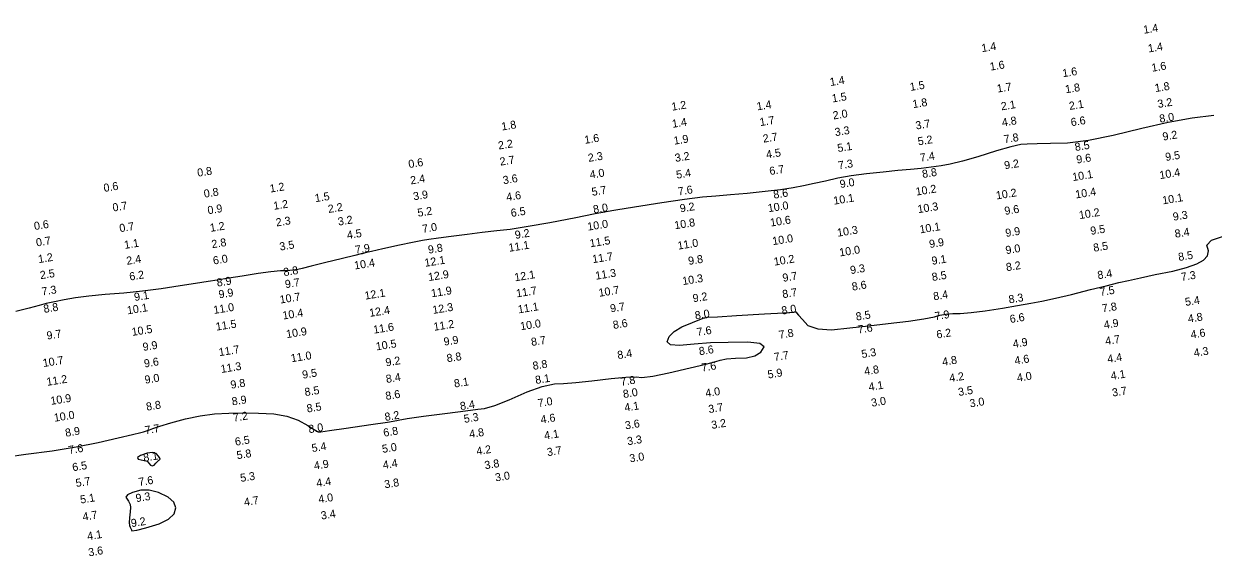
# Model space of a CAD drawing. Extents: x 988130 to 1132882, y 654656 to 841453.
# Drawn here: x 1107874 to 1108617, y 666534 to 666867 of the extents above; entities that cross this region are included whole.
import ezdxf

# ---------------------------------------------------------------- set-up
doc = ezdxf.new("R2010")
doc.units = 0
doc.layers.add('V-TOPO-MAJR', color=7, linetype='Continuous')
doc.layers.add('V-TOPO-SOUN', color=7, linetype='Continuous')

msp = doc.modelspace()

# ---------------------------------------------------------------- linework, layer by layer
at = {"layer": 'V-TOPO-MAJR'}
for points in [[(1108617.19, 666809.85), (1108603.62, 666808.13), (1108588.62, 666805.46), (1108572.17, 666801.85), (1108554.27, 666797.3), (1108538.79, 666794.21), (1108525.72, 666792.58), (1108515.07, 666792.43), (1108506.66, 666792.23), (1108500.51, 666791.99), (1108496.61, 666791.72), (1108490.18, 666790.31), (1108481.23, 666787.75), (1108469.76, 666784.06), (1108460.17, 666781.28), (1108452.48, 666779.4), (1108446.66, 666778.42), (1108440.57, 666777.57), (1108434.18, 666776.84), (1108427.51, 666776.22), (1108419.6, 666775.45), (1108410.44, 666774.53), (1108400.04, 666773.45), (1108390.59, 666772.15), (1108382.11, 666770.64), (1108374.58, 666768.92), (1108367.44, 666767.35), (1108360.69, 666765.94), (1108354.33, 666764.69), (1108346.33, 666763.48), (1108336.7, 666762.31), (1108325.44, 666761.2), (1108315.18, 666760.24), (1108305.92, 666759.44), (1108297.67, 666758.79), (1108286.46, 666757.43), (1108272.29, 666755.35), (1108255.16, 666752.56), (1108243.55, 666750.68), (1108237.45, 666749.7), (1108236.87, 666749.62), (1108236.3, 666749.54), (1108235.74, 666749.44), (1108235.19, 666749.33), (1108229.42, 666748.2), (1108218.44, 666746.04), (1108202.24, 666742.87), (1108188.61, 666740.43), (1108177.54, 666738.73), (1108169.04, 666737.77), (1108160.05, 666736.7), (1108150.58, 666735.53), (1108140.61, 666734.26), (1108132.63, 666733.22), (1108126.64, 666732.4), (1108122.64, 666731.8), (1108116.51, 666730.62), (1108108.24, 666728.87), (1108097.84, 666726.53), (1108090.7, 666724.91), (1108086.8, 666723.99), (1108086.17, 666723.79), (1108085.56, 666723.63), (1108084.97, 666723.52), (1108084.42, 666723.45), (1108080.32, 666722.48), (1108072.67, 666720.6), (1108061.48, 666717.81), (1108053.11, 666715.73), (1108047.56, 666714.36), (1108044.85, 666713.69), (1108041.66, 666713.21), (1108038, 666712.89), (1108033.87, 666712.75), (1108027.83, 666712.15), (1108019.89, 666711.09), (1108010.05, 666709.56), (1108001.56, 666708.22), (1107994.44, 666707.08), (1107988.68, 666706.13), (1107980.92, 666704.91), (1107971.17, 666703.42), (1107959.43, 666701.66), (1107947.71, 666700.17), (1107936.01, 666698.95), (1107924.32, 666698.01), (1107914.24, 666696.99), (1107905.76, 666695.9), (1107898.87, 666694.73), (1107892.82, 666693.55), (1107887.59, 666692.36), (1107883.19, 666691.15), (1107876.86, 666689.52), (1107868.62, 666687.46)], [(1107863.46, 666596.67), (1107874.78, 666598.17), (1107891.23, 666600.35), (1107906.34, 666602.78), (1107920.1, 666605.47), (1107932.53, 666608.41), (1107941.38, 666610.52), (1107946.65, 666611.8), (1107948.34, 666612.24), (1107950.14, 666612.82), (1107952.06, 666613.52), (1107954.09, 666614.35), (1107958.51, 666615.78), (1107965.33, 666617.79), (1107974.54, 666620.4), (1107983.67, 666622.28), (1107992.73, 666623.44), (1108001.71, 666623.89), (1108010.87, 666624.04), (1108020.2, 666623.9), (1108029.71, 666623.47), (1108038, 666622.03), (1108045.07, 666619.57), (1108050.92, 666616.1), (1108054.9, 666613.74), (1108057.01, 666612.49), (1108057.26, 666612.36), (1108057.45, 666612.27), (1108057.6, 666612.21), (1108057.69, 666612.19), (1108057.82, 666612.18), (1108057.99, 666612.19), (1108058.2, 666612.22), (1108058.46, 666612.25), (1108058.79, 666612.27), (1108059.18, 666612.3), (1108064.56, 666613.04), (1108074.94, 666614.5), (1108090.31, 666616.68), (1108100.86, 666618.25), (1108106.6, 666619.21), (1108107.51, 666619.57), (1108113.1, 666620.46), (1108123.34, 666621.89), (1108138.26, 666623.84), (1108149.57, 666625.31), (1108157.29, 666626.28), (1108161.4, 666626.76), (1108167.91, 666628.73), (1108176.81, 666632.18), (1108188.1, 666637.13), (1108197.51, 666640.48), (1108205.05, 666642.26), (1108210.72, 666642.45), (1108218.52, 666643.04), (1108228.45, 666644.04), (1108240.51, 666645.44), (1108249.75, 666646.27), (1108256.18, 666646.53), (1108259.78, 666646.22), (1108266.6, 666647.05), (1108276.63, 666649.02), (1108289.89, 666652.13), (1108299.64, 666654.51), (1108305.87, 666656.16), (1108308.58, 666657.07), (1108312.68, 666657.77), (1108318.16, 666658.24), (1108325.02, 666658.5), (1108330.3, 666659.76), (1108333.99, 666662), (1108336.1, 666665.23), (1108333.42, 666667.33), (1108325.96, 666668.3), (1108313.72, 666668.13), (1108302.52, 666667.72), (1108292.37, 666667.07), (1108283.25, 666666.18), (1108277.63, 666666.66), (1108275.5, 666668.52), (1108276.86, 666671.74), (1108279.96, 666674.81), (1108284.81, 666677.73), (1108291.4, 666680.49), (1108296, 666682.37), (1108298.59, 666683.38), (1108299.18, 666683.51), (1108299.76, 666683.62), (1108300.31, 666683.71), (1108300.84, 666683.78), (1108307.04, 666684.17), (1108318.91, 666684.88), (1108336.44, 666685.91), (1108348.36, 666686.63), (1108354.68, 666687.04), (1108355.39, 666687.14), (1108355.93, 666687.1), (1108356.28, 666686.92), (1108356.45, 666686.6), (1108357.71, 666685.12), (1108360.07, 666682.47), (1108363.53, 666678.66), (1108369.6, 666676.51), (1108378.29, 666676.01), (1108389.6, 666677.16), (1108401.38, 666678.43), (1108413.65, 666679.84), (1108426.39, 666681.37), (1108436, 666682.76), (1108442.49, 666684), (1108445.86, 666685.09), (1108449.68, 666685.82), (1108453.96, 666686.17), (1108458.69, 666686.15), (1108465.45, 666686.71), (1108474.22, 666687.86), (1108485.01, 666689.58), (1108494.51, 666691.15), (1108502.71, 666692.58), (1108509.61, 666693.87), (1108518.13, 666695.72), (1108528.28, 666698.13), (1108540.05, 666701.11), (1108549.88, 666703.55), (1108557.77, 666705.46), (1108563.73, 666706.83), (1108571.33, 666708.49), (1108580.57, 666710.43), (1108591.46, 666712.66), (1108600.12, 666714.92), (1108606.55, 666717.21), (1108610.75, 666719.53), (1108613.17, 666722.26), (1108613.8, 666725.39), (1108612.65, 666728.93), (1108615.75, 666731.97), (1108623.11, 666734.5)]]:
    msp.add_lwpolyline(points, dxfattribs=at)
for points in [[(1107950.61, 666593.94), (1107952.68, 666591.46), (1107953.76, 666591.03), (1107954.91, 666591.42), (1107956.11, 666592.63), (1107956.96, 666593.51), (1107957.47, 666594.07), (1107957.63, 666594.3), (1107957.89, 666594.54), (1107958.24, 666594.78), (1107958.69, 666595.03), (1107958.52, 666595.77), (1107957.72, 666597.01), (1107956.31, 666598.75), (1107953.95, 666599.38), (1107950.66, 666598.9), (1107946.42, 666597.32), (1107944.53, 666596.06), (1107944.99, 666595.13)], [(1107938.97, 666568.91), (1107940.05, 666566.88), (1107940.23, 666564.96), (1107940.06, 666562.15), (1107939.53, 666558.43), (1107939.35, 666555.61), (1107939.51, 666553.68), (1107940.01, 666552.65), (1107940.45, 666551.74), (1107940.81, 666550.95), (1107941.11, 666550.27), (1107944.08, 666550.66), (1107949.72, 666552.12), (1107958.03, 666554.64), (1107963.94, 666557.59), (1107967.44, 666560.95), (1107968.55, 666564.74), (1107967.29, 666568.23), (1107963.66, 666571.43), (1107957.68, 666574.33), (1107951.98, 666575.76), (1107946.57, 666575.73), (1107941.46, 666574.23), (1107938.34, 666572.81), (1107937.21, 666571.46)]]:
    msp.add_lwpolyline(points, close=True, dxfattribs=at)

# ---------------------------------------------------------------- texts
at = {"layer": 'V-TOPO-SOUN'}
for s, p in [('1.4', (1108573.45, 666860.96)), ('1.4', (1108472.3, 666849.5)), ('1.4', (1108576.4, 666849.29)), ('1.6', (1108477.54, 666837.92)), ('1.6', (1108578.56, 666837.23)), ('1.6', (1108522.86, 666833.8)), ('1.4', (1108377.56, 666828.3)), ('1.5', (1108427.55, 666825.25)), ('1.7', (1108481.96, 666824.19)), ('1.8', (1108524.63, 666823.77)), ('1.8', (1108580.63, 666824.56)), ('1.5', (1108378.84, 666818.03)), ('1.2', (1108278.63, 666812.87)), ('1.4', (1108331.89, 666813.09)), ('1.8', (1108429.23, 666814.47)), ('2.1', (1108484.48, 666813.11)), ('2.1', (1108527.04, 666813.35)), ('3.2', (1108582.34, 666814.58)), ('1.8', (1108172.35, 666800.5)), ('1.4', (1108278.96, 666802.17)), ('1.7', (1108333.73, 666803.25)), ('2.0', (1108379.43, 666807.4)), ('3.7', (1108431.13, 666801.14)), ('4.8', (1108485.07, 666803.03)), ('6.6', (1108528.11, 666803.16)), ('8.0', (1108583.48, 666805.37)), ('2.7', (1108335.72, 666792.9)), ('3.3', (1108380.66, 666796.97)), ('9.2', (1108585.47, 666794.19)), ('2.2', (1108170.3, 666788.61)), ('1.6', (1108224.2, 666792.16)), ('1.9', (1108279.97, 666791.64)), ('5.1', (1108382.27, 666787.02)), ('5.2', (1108432.52, 666791.21)), ('7.8', (1108486.29, 666792.55)), ('8.5', (1108530.63, 666787.67)), ('2.7', (1108171.34, 666778.53)), ('2.3', (1108226.46, 666780.89)), ('3.2', (1108280.73, 666780.87)), ('4.5', (1108337.72, 666782.99)), ('7.4', (1108433.87, 666780.99)), ('9.6', (1108531.6, 666779.82)), ('9.5', (1108587.16, 666781.44)), ('0.8', (1107982.3, 666771.6)), ('0.6', (1108114.25, 666777)), ('4.0', (1108227.51, 666770.4)), ('6.7', (1108339.8, 666772.68)), ('7.3', (1108382.75, 666776.17)), ('8.8', (1108435.22, 666770.81)), ('9.2', (1108486.55, 666776.23)), ('10.4 ', (1108583.53, 666770.13)), ('2.4', (1108115.42, 666766.8)), ('3.6', (1108173.28, 666766.93)), ('5.4', (1108281.56, 666770.34)), ('9.0', (1108383.78, 666764.52)), ('10.1 ', (1108529.06, 666768.9)), ('0.6', (1107923.77, 666762.11)), ('0.8', (1107986.43, 666758.49)), ('1.2', (1108027.59, 666761.71)), ('1.5', (1108055.75, 666755.72)), ('3.9', (1108117.23, 666756.87)), ('4.6', (1108175.39, 666756.37)), ('5.7', (1108228.72, 666759.65)), ('7.6', (1108282.64, 666759.89)), ('8.6', (1108342.26, 666757.89)), ('10.2 ', (1108431.23, 666759.82)), ('10.2 ', (1108481.39, 666757.41)), ('10.4 ', (1108530.98, 666758.03)), ('0.7', (1107929.39, 666749.86)), ('0.9', (1107988.75, 666748.15)), ('1.2', (1108029.86, 666750.91)), ('2.2', (1108063.97, 666748.96)), ('8.0', (1108229.68, 666748.71)), ('9.2', (1108283.86, 666749.33)), ('10.0 ', (1108338.84, 666749.43)), ('10.1 ', (1108379.81, 666754.15)), ('10.3 ', (1108432.4, 666748.82)), ('10.1 ', (1108585.32, 666754.36)), ('3.2', (1108070.19, 666741.06)), ('5.2', (1108119.9, 666746.58)), ('6.5', (1108178.21, 666746.46)), ('10.6 ', (1108340.28, 666740.45)), ('9.6', (1108486.67, 666747.74)), ('10.2 ', (1108533.26, 666745.14)), ('9.3', (1108591.91, 666744.12)), ('0.6', (1107880.31, 666738.27)), ('0.7', (1107933.65, 666736.94)), ('1.2', (1107990.21, 666737.15)), ('2.3', (1108031.43, 666740.52)), ('7.0', (1108122.87, 666736.52)), ('10.0 ', (1108226.07, 666737.92)), ('10.8 ', (1108280.44, 666738.78)), ('10.3 ', (1108382.13, 666734.12)), ('10.1 ', (1108433.64, 666736.21)), ('9.9', (1108487.25, 666733.97)), ('9.5', (1108540.35, 666735.28)), ('8.4', (1108593.1, 666733.47)), ('0.7', (1107881.57, 666728.01)), ('1.1', (1107936.65, 666726.5)), ('2.8', (1107991.24, 666726.94)), ('4.5', (1108075.84, 666732.62)), ('9.2', (1108180.77, 666732.73)), ('11.5 ', (1108227.51, 666727.52)), ('11.0 ', (1108282.43, 666726.05)), ('10.0 ', (1108341.66, 666728.86)), ('9.9', (1108439.64, 666727.05)), ('3.5', (1108033.72, 666725.47)), ('7.9', (1108080.93, 666723.45)), ('9.8', (1108126.48, 666723.52)), ('11.1 ', (1108176.84, 666724.69)), ('10.0 ', (1108383.51, 666721.78)), ('9.0', (1108487.37, 666723.2)), ('8.5', (1108542.16, 666724.72)), ('8.5', (1108595.26, 666718.97)), ('1.2', (1107882.87, 666717.64)), ('2.4', (1107938.02, 666716.55)), ('6.0', (1107992.14, 666716.73)), ('10.4 ', (1108080.37, 666713.64)), ('12.1 ', (1108124.31, 666715.3)), ('11.7 ', (1108229.12, 666717.59)), ('9.8', (1108289.08, 666716.49)), ('10.2 ', (1108342.56, 666716.04)), ('9.1', (1108441.17, 666716.55)), ('8.2', (1108487.67, 666712.57)), ('2.5', (1107884.05, 666707.57)), ('6.2', (1107939.88, 666706.72)), ('8.8', (1108036.13, 666709.48)), ('12.9 ', (1108126.58, 666706.41)), ('12.1 ', (1108180.5, 666706.25)), ('11.3 ', (1108231.07, 666707.24)), ('10.3 ', (1108285.4, 666703.91)), ('9.7', (1108348, 666705.93)), ('9.3', (1108390.26, 666710.74)), ('8.5', (1108441.3, 666706.43)), ('8.4', (1108544.81, 666707.57)), ('7.3', (1108596.98, 666706.5)), ('7.3', (1107885.11, 666697.37)), ('8.9', (1107994.45, 666702.92)), ('9.7', (1108037.12, 666701.94)), ('11.9 ', (1108128.42, 666696.27)), ('11.7 ', (1108181.57, 666696.21)), ('10.7 ', (1108233.12, 666696.58)), ('8.6', (1108391.31, 666700.41)), ('7.5', (1108546.26, 666697.08)), ('9.1', (1107942.86, 666693.91)), ('9.9', (1107995.65, 666695.59)), ('10.7 ', (1108033.84, 666692.36)), ('12.1 ', (1108086.86, 666694.79)), ('9.2', (1108291.89, 666693.14)), ('8.7', (1108347.88, 666695.71)), ('8.4', (1108442.17, 666694.36)), ('8.3', (1108489.28, 666692.45)), ('5.4', (1108599.5, 666690.83)), ('8.8', (1107886.24, 666686.52)), ('10.1 ', (1107938.42, 666685.6)), ('11.0 ', (1107992.4, 666685.87)), ('10.4 ', (1108035.59, 666682.37)), ('12.4 ', (1108089.79, 666684.02)), ('12.3 ', (1108129.29, 666685.88)), ('11.1 ', (1108182.65, 666686.2)), ('9.7', (1108240.28, 666686.8)), ('8.0', (1108293.22, 666682.42)), ('8.0', (1108347.37, 666685.46)), ('8.5', (1108393.8, 666681.7)), ('7.9', (1108443.08, 666681.95)), ('7.8', (1108547.65, 666686.84)), ('11.5 ', (1107993.89, 666675.4)), ('11.6 ', (1108092.27, 666673.53)), ('11.2 ', (1108129.96, 666675.31)), ('10.0 ', (1108184.1, 666675.68)), ('8.6', (1108242.01, 666676.45)), ('6.6', (1108490, 666680.17)), ('4.9', (1108548.74, 666676.57)), ('4.8', (1108601.28, 666680.39)), ('9.7', (1107888.2, 666669.82)), ('10.5 ', (1107941.35, 666672.13)), ('10.9 ', (1108037.87, 666670.75)), ('7.6', (1108294.41, 666672.02)), ('7.8', (1108345.69, 666670.32)), ('7.6', (1108395.01, 666673.59)), ('6.2', (1108444.18, 666670.49)), ('4.7', (1108549.66, 666666.43)), ('4.6', (1108603.01, 666670.44)), ('9.9', (1107948.22, 666662.74)), ('11.7 ', (1107995.74, 666659.46)), ('10.5 ', (1108093.89, 666663.05)), ('9.9', (1108136.27, 666666)), ('8.7', (1108190.89, 666665.84)), ('8.6', (1108295.77, 666660.02)), ('4.9', (1108491.9, 666664.64)), ('4.3', (1108604.95, 666659.06)), ('10.7 ', (1107885.8, 666652.69)), ('9.6', (1107949.04, 666652.38)), ('11.0 ', (1108040.8, 666655.67)), ('9.2', (1108099.97, 666653.08)), ('8.8', (1108138.18, 666655.66)), ('8.4', (1108244.83, 666657.63)), ('7.7', (1108342.66, 666656.43)), ('5.3', (1108397.27, 666658.27)), ('4.8', (1108447.77, 666653.44)), ('4.6', (1108492.96, 666654.18)), ('4.4', (1108550.95, 666655.18)), ('11.3 ', (1107996.93, 666648.96)), ('9.5', (1108047.88, 666645.38)), ('8.8', (1108191.89, 666650.91)), ('7.6', (1108297.33, 666649.84)), ('5.9', (1108338.69, 666645.51)), ('4.8', (1108399.03, 666647.53)), ('4.1', (1108553.07, 666644.66)), ('11.2 ', (1107888.16, 666640.91)), ('9.0', (1107949.42, 666642.25)), ('9.8', (1108003.1, 666639.1)), ('8.4', (1108100.18, 666642.72)), ('8.1', (1108142.73, 666639.88)), ('8.1', (1108193.47, 666642.07)), ('7.8', (1108246.77, 666640.91)), ('4.1', (1108401.81, 666637.77)), ('4.2', (1108452.2, 666643.26)), ('4.0', (1108494.47, 666643.47)), ('10.9 ', (1107890.61, 666629.02)), ('8.5', (1108049.37, 666634.5)), ('8.6', (1108099.91, 666632.1)), ('8.0', (1108248.32, 666633.3)), ('4.0', (1108299.79, 666633.85)), ('3.5', (1108457.75, 666634.56)), ('3.7', (1108553.94, 666634.2)), ('8.8', (1107950.36, 666625.4)), ('8.9', (1108003.89, 666628.66)), ('8.5', (1108050.7, 666624.26)), ('8.4', (1108146.51, 666625.74)), ('7.0', (1108195.08, 666627.6)), ('4.1', (1108249.19, 666624.83)), ('3.7', (1108301.66, 666623.87)), ('3.0', (1108403.4, 666627.86)), ('3.0', (1108464.9, 666627.43)), ('10.0 ', (1107892.73, 666618.49)), ('7.2', (1108004.7, 666618.54)), ('8.2', (1108099.4, 666618.98)), ('5.3', (1108148.87, 666617.77)), ('4.6', (1108196.84, 666617.35)), ('8.9', (1107899.78, 666609.07)), ('7.7', (1107949.54, 666610.7)), ('8.0', (1108051.8, 666611.34)), ('6.8', (1108098.57, 666609.13)), ('4.8', (1108152.25, 666608.27)), ('4.1', (1108199.07, 666607.32)), ('3.6', (1108249.56, 666613.7)), ('3.2', (1108303.5, 666613.96)), ('6.5', (1108005.86, 666603.5)), ('5.4', (1108053.76, 666599.51)), ('3.3', (1108250.92, 666603.78)), ('7.6', (1107901.83, 666598.3)), ('8.1', (1107948.58, 666593.53)), ('5.8', (1108006.9, 666595.06)), ('5.0', (1108097.78, 666598.99)), ('4.2', (1108156.72, 666597.61)), ('3.7', (1108200.82, 666596.97)), ('3.0', (1108252.38, 666593.06)), ('6.5', (1107904.22, 666587.53)), ('4.9', (1108055.22, 666588.51)), ('4.4', (1108098.25, 666588.96)), ('3.8', (1108161.8, 666588.81)), ('5.7', (1107906.32, 666577.69)), ('7.6', (1107945.6, 666578.33)), ('5.3', (1108009.16, 666580.86)), ('4.4', (1108056.72, 666577.6)), ('3.0', (1108168.43, 666581.16)), ('3.8', (1108099.19, 666576.87)), ('5.1', (1107909.15, 666567.33)), ('9.3', (1107943.83, 666568.22)), ('4.7', (1108011.51, 666565.77)), ('4.0', (1108057.97, 666567.55)), ('4.7', (1107910.67, 666556.63)), ('3.4', (1108059.54, 666557.35)), ('9.2', (1107940.88, 666552.6)), ('4.1', (1107913.54, 666544.47)), ('3.6', (1107914.22, 666534.35))]:
    msp.add_text(s, height=5, rotation=9.0039, dxfattribs=at).set_placement(p)

doc.saveas('drawing.dxf')
